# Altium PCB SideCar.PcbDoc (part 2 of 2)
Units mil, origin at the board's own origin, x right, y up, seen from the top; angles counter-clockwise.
Board outline 4800 x 2800 mil, 4 copper layers (Top Layer, GND Plane, Power Routing, Bottom Layer), stack 61.4 mil thick; 116 components, 136 nets, 590 pads, 115 vias.
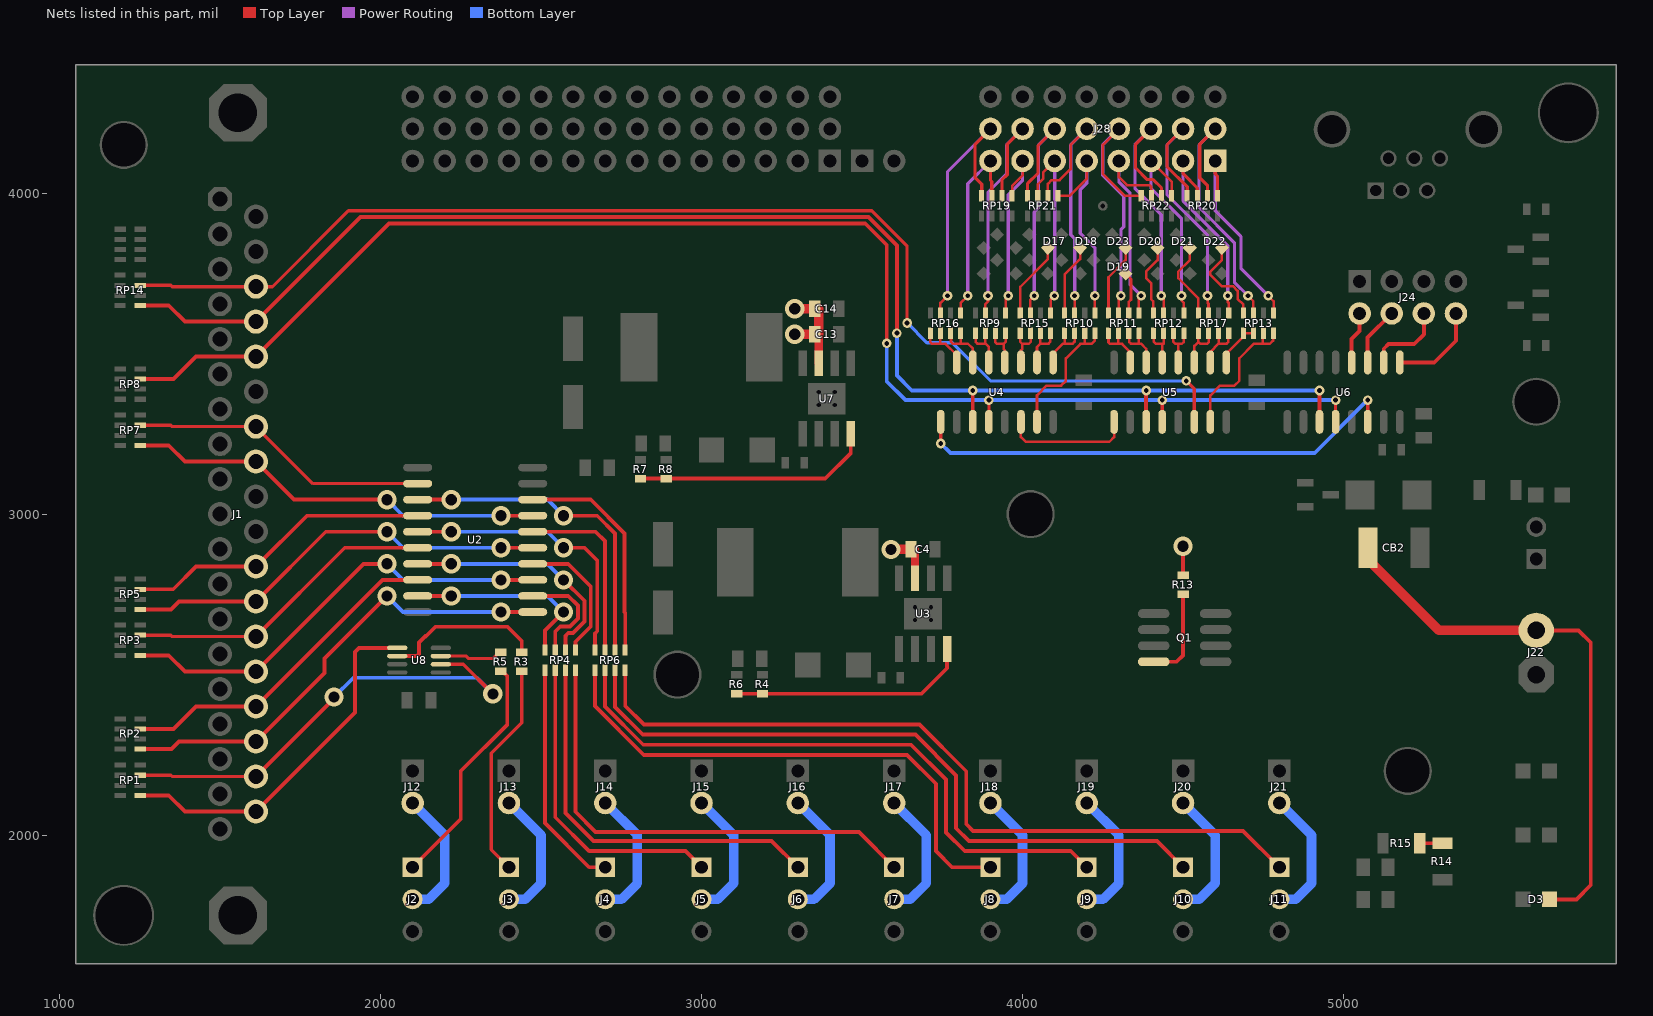
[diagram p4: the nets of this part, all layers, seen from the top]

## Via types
v1: diameter 60, hole 35, Top Layer to Bottom Layer, 60 vias
v2: diameter 30, hole 15, Top Layer to Bottom Layer, 39 vias
v3: diameter 35, hole 15, Top Layer to Bottom Layer, 10 vias
v4: diameter 40, hole 20, Top Layer to Bottom Layer, 6 vias

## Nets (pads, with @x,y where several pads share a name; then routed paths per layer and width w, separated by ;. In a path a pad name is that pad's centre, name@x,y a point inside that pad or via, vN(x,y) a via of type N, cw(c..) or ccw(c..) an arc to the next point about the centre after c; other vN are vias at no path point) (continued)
NetD17_A: D17.A RP15.7 | length 238.4
  Top Layer w8: RP15.7@3992.76,3626.5 3992.76,3707.76 4079.12,3794.12 D17.A@4079.12,3829.12
NetD18_A: D18.A RP10.7 | length 222.7
  Top Layer w8: RP10.7@4130.75,3626.5 4130.75,3745.75 4179.12,3794.12 D18.A@4179.12,3829.12
NetD19_A: D19.A RP11.3 | length 132.5
  Top Layer w8: D19.A@4320.88,3749.12 4337.76,3732.24 4337.76,3667.76 4330.75,3660.75 RP11.3@4330.75,3626.5
NetD20_A: D20.A RP12.7 | length 226.9
  Top Layer w8: RP12.7@4407.76,3626.5 4407.76,3662.24 4400.75,3669.25 4400.75,3719.25 4385,3735 4385,3755 4420.88,3790.88 D20.A@4420.88,3829.12
NetD21_A: D21.A RP17.7 | length 243.5
  Top Layer w8: D21.A@4520.88,3829.12 4520.88,3790.88 4485,3755 4485,3735 4547.76,3672.24 RP17.7@4547.76,3626.5
NetD22_A: D22.A RP13.7 | length 280.6
  Top Layer w8: D22.A@4620.88,3829.12 4620.88,3790.88 4585,3755 4585,3745 4620,3710 4655,3710 4670,3695 4670,3670 4687.76,3652.24 RP13.7@4687.76,3626.5
NetD23_A: D23.A RP11.7 | length 224.6
  Top Layer w8: RP11.7@4267.76,3626.5 4267.76,3737.76 4320.88,3790.88 D23.A@4320.88,3829.12
NetJ2_1: J2.1 R5.1 | length 731.3
  Top Layer w12: J2.1@2100,1900 2250,2050 2250,2200 2395,2345 2395,2495 R5.1@2385,2505
NetJ2_2: J2.2 J12.2 | length 412.1
  Bottom Layer w30: J2.2@2100,1800 2150,1800 2200,1850 2200,2000 J12.2@2100,2100
NetJ3_1: J3.1 R3.1 | length 672.6
  Top Layer w10: J3.1@2400,1900 2345,1955 2345,2255 2440,2350 R3.1@2440,2510.47
NetJ3_2: J3.2 J13.2 | length 412.1
  Bottom Layer w30: J3.2@2400,1800 2450,1800 2500,1850 2500,2000 J13.2@2400,2100
NetJ4_1: J4.1 RP4.1 | length 720.4
  Top Layer w12: RP4.1@2512.76,2513.5 2512.76,2037.24 2650,1900 J4.1@2700,1900
NetJ4_2: J4.2 J14.2 | length 412.1
  Bottom Layer w30: J4.2@2700,1800 2750,1800 2800,1850 2800,2000 J14.2@2700,2100
NetJ5_1: J5.1 RP4.3 | length 978
  Top Layer w12: RP4.3@2544.25,2513.5 2544.25,2055.75 2650,1950 2950,1950 J5.1@3000,1900
NetJ5_2: J5.2 J15.2 | length 412.1
  Bottom Layer w30: J5.2@3000,1800 3050,1800 3100,1850 3100,2000 J15.2@3000,2100
NetJ6_1: J6.1 RP4.5 | length 1238.9
  Top Layer w12: RP4.5@2575.75,2513.5 2575.75,2068.79 2663.05,1981.5 3218.5,1981.5 J6.1@3300,1900
NetJ6_2: J6.2 J16.2 | length 412.1
  Bottom Layer w30: J6.2@3300,1800 3350,1800 3400,1850 3400,2000 J16.2@3300,2100
NetJ7_1: J7.1 RP4.7 | length 1505.1
  Top Layer w12: RP4.7@2607.24,2513.5 2607.24,2072.76 2670,2010 3490,2010 J7.1@3600,1900
NetJ7_2: J7.2 J17.2 | length 412.1
  Bottom Layer w30: J7.2@3600,1800 3650,1800 3700,1850 3700,2000 J17.2@3600,2100
NetJ8_1: J8.1 RP6.1 | length 1674.6
  Top Layer w12: RP6.1@2667.76,2513.5 2667.76,2402.24 2820,2250 3640,2250 3730,2160 3730,1950 3780,1900 J8.1@3900,1900
NetJ8_2: J8.2 J18.2 | length 412.1
  Bottom Layer w30: J8.2@3900,1800 3950,1800 4000,1850 4000,2000 J18.2@3900,2100
NetJ9_1: J9.1 RP6.3 | length 1917.3
  Top Layer w12: RP6.3@2699.25,2513.5 2699.25,2400.75 2818.5,2281.5 3653.05,2281.5 3761.5,2173.05 3761.5,2008.5 3820,1950 4150,1950 J9.1@4200,1900
NetJ9_2: J9.2 J19.2 | length 412.1
  Bottom Layer w30: J9.2@4200,1800 4250,1800 4300,1850 4300,2000 J19.2@4200,2100
NetJ10_1: J10.1 RP6.5 | length 2186.7
  Top Layer w12: RP6.5@2730.75,2513.5 2730.75,2399.25 2817.01,2312.99 3666.09,2312.99 3792.99,2186.09 3792.99,2021.55 3833.05,1981.5 4418.5,1981.5 J10.1@4500,1900
NetJ10_2: J10.2 J20.2 | length 412.1
  Bottom Layer w30: J10.2@4500,1800 4550,1800 4600,1850 4600,2000 J20.2@4500,2100
NetJ11_1: J11.1 RP6.7 | length 2453.1
  Top Layer w12: RP6.7@2762.24,2513.5 2762.24,2402.76 2820.51,2344.49 3679.14,2344.49 3824.49,2199.14 3824.49,2034.6 3846.09,2012.99 4687.01,2012.99 J11.1@4800,1900
NetJ11_2: J11.2 J21.2 | length 412.1
  Bottom Layer w30: J11.2@4800,1800 4850,1800 4900,1850 4900,2000 J21.2@4800,2100
NetJ24_2: J24.2 U6.4 | length 162.8
  Top Layer w12: U6.4@5025,3472.52 5025,3545 5050,3570 J24.2@5050,3625
NetJ24_4: J24.4 U6.3 | length 183.5
  Top Layer w12: U6.3@5075,3472.52 5075,3550 J24.4@5150,3625
NetJ24_6: J24.6 U6.2 | length 251.1
  Top Layer w12: U6.2@5125,3472.52 5125,3515 5140,3530 5220,3530 5250,3560 J24.6@5250,3625
NetJ24_8: J24.8 U6.1 | length 288
  Top Layer w12: U6.1@5175,3472.52 5282.52,3472.52 5350,3540 J24.8@5350,3625
NetQ1_G: Q1.G R13.1 | length 289.7
  Top Layer w12: Q1.G@4408.54,2540 4480,2540 4500,2560 R13.1@4500,2750
NetR3_2: R3.2 U8.6 | length 500.7
  Top Layer w12: U8.6@2052.09,2557.8 2113.11,2557.8 2120,2564.69 2120,2600 2140,2620 ; 2140,2617.83 2171.42,2649.25 2395.75,2649.25 2440,2605 R3.2@2440,2570
NetR4_1: R4.1 R6.2 U3.4 | length 747.9
  Top Layer w12: R6.2@3110,2440.47 R4.1@3190,2440.47 3685.47,2440.47 3765,2520 U3.4@3765,2580
NetR5_2: R5.2 U8.3 | length 186.5
  Top Layer w10: U8.3@2187.91,2557.8 2267.2,2557.8 2275,2550 2350,2550 R5.2@2365,2565
NetR7_2: R7.2 R8.1 U7.4 | length 747.9
  Top Layer w12: R7.2@2810,3110.47 R8.1@2890,3110.47 3385.47,3110.47 3465,3190 U7.4@3465,3250
NetR14_1: R14.1 R15.2 | length 70.8
  Top Layer w10: R15.2@5237.09,1975 R14.1@5307.91,1975
NetRP4_2: RP4.2 U2.9 | length 631.2
  Top Layer w12: U2.9@2115.87,2745 v1(2220,2745) ; RP4.2@2512.76,2576.5 2512.76,2637.76 v1(2570,2695) v1@2580,2685
  Bottom Layer w12: v1(2220,2745) 2520,2745 v1(2570,2695)
NetRP4_4: RP4.4 U2.12 | length 338.7
  Top Layer w12: U2.12@2474.13,2745 2475,2745 2585,2745 2615,2715 2615,2675 2590,2650 2560,2650 2544.25,2634.25 RP4.4@2544.25,2576.5
NetRP4_6: RP4.6 U2.7 | length 753.6
  Top Layer w12: U2.7@2115.87,2845 v1(2220,2845) ; v1(2570,2795) 2635,2730 2635,2665 2600,2630 2585,2630 2575.75,2620.75 RP4.6@2575.75,2576.5
  Bottom Layer w12: v1(2220,2845) 2520,2845 v1(2570,2795)
NetRP4_8: RP4.8 U2.14 | length 422.3
  Top Layer w12: U2.14@2480,2845 2585,2845 2655,2775 2655,2650 2607.24,2602.24 RP4.8@2607.24,2576.5
NetRP6_2: RP6.2 U2.5 | length 877.9
  Top Layer w12: U2.5@2115.87,2945 v1(2220,2945) ; v1(2570,2895) 2635,2895 2675,2855 2675,2635 2667.76,2627.76 RP6.2@2667.76,2576.5
  Bottom Layer w12: v1(2220,2945) 2520,2945 v1(2570,2895)
NetRP6_4: RP6.4 U2.16 | length 576.5
  Top Layer w12: U2.16@2474.13,2945 2670,2945 2699.25,2915.75 RP6.4@2699.25,2576.5
NetRP6_6: RP6.6 U2.3 | length 1021.4
  Top Layer w12: U2.3@2115.87,3045 v1(2220,3045) ; v1(2570,2995) 2675,2995 2730.75,2939.25 RP6.6@2730.75,2576.5
  Bottom Layer w12: v1(2220,3045) 2520,3045 v1(2570,2995)
NetRP6_8: RP6.8 U2.18 | length 693.8
  Top Layer w12: U2.18@2474.13,3045 2655,3045 2760,2940 2760,2695 2762.24,2692.76 RP6.8@2762.24,2576.5
NetRP9_2: RP9.2 RP9.4 U4.4 | length 233.7
  Top Layer w8: RP9.4@3915.75,3563.5 RP9.4@3914.49,3563.5 ; U4.4@3945,3472.52 3945,3510 3940.75,3514.25 3940.75,3530 ; RP9.2@3947.24,3563.5 3947.24,3536.5 3940.75,3530 ; 3914.49,3536.5 RP9.4@3914.49,3563.5 ; 3914.49,3536.5 RP9.4@3914.49,3563.5 ; 3914.49,3536.5 RP9.4@3914.49,3563.5 ; 3914.49,3536.5 RP9.4@3914.49,3563.5 ; 3914.49,3536.5 3920.98,3530 3940.75,3530
NetRP9_6: RP9.6 RP9.8 U4.5 | length 242.7
  Top Layer w8: RP9.8@3852.76,3563.5 RP9.8@3854.02,3564.76 ; RP9.6@3884.25,3563.5 3884.25,3531.26 ; U4.5@3895,3472.52 3895,3520.51 3884.25,3531.26 ; 3854.02,3536.5 RP9.8@3854.02,3563.5 ; 3854.02,3536.5 RP9.8@3854.02,3563.5 ; 3854.02,3536.5 RP9.8@3854.02,3563.5 ; 3854.02,3536.5 RP9.8@3854.02,3563.5 ; 3854.02,3536.5 3859.25,3531.26 3884.25,3531.26 ; RP9.8@3854.02,3563.5 RP9.8@3854.02,3564.76 ; RP9.8@3854.02,3563.5 RP9.8@3854.02,3564.76 ; RP9.8@3854.02,3563.5 RP9.8@3854.02,3564.76 ; RP9.8@3854.02,3563.5 RP9.8@3854.02,3564.76
NetRP10_2: RP10.2 RP10.4 U4.15 | length 429.8
  Top Layer w8: U4.15@4045,3287.48 4045,3370 4075,3400 4120,3400 4135,3415 4135,3485 4180,3530 4215,3530 4225.24,3540.24 RP10.2@4225.24,3563.5 ; 4193.74,3531.26 RP10.4@4193.74,3563.5
NetRP10_6: RP10.6 RP10.8 U4.1 | length 142.8
  Top Layer w8: U4.1@4095,3500 4125,3530 4129.88,3530 ; RP10.8@4130.75,3563.5 4130.75,3530.75 4129.88,3530 ; RP10.6@4162.24,3563.5 4162.24,3537.24 4155,3530 4129.88,3530
NetRP11_2: RP11.2 RP11.4 U5.6 | length 251.5
  Top Layer w8: RP11.4@4330.75,3563.5 RP11.4@4332.01,3564.76 ; RP11.2@4362.24,3563.5 4362.24,3531.26 ; U5.6@4385,3472.52 4385,3515 4368.74,3531.26 4362.24,3531.26 ; 4332.01,3536.5 RP11.4@4332.01,3563.5 ; 4332.01,3536.5 RP11.4@4332.01,3563.5 ; 4332.01,3536.5 RP11.4@4332.01,3563.5 ; 4332.01,3536.5 RP11.4@4332.01,3563.5 ; 4332.01,3536.5 4337.24,3531.26 4362.24,3531.26 ; RP11.4@4332.01,3563.5 RP11.4@4332.01,3564.76 ; RP11.4@4332.01,3563.5 RP11.4@4332.01,3564.76 ; RP11.4@4332.01,3563.5 RP11.4@4332.01,3564.76 ; RP11.4@4332.01,3563.5 RP11.4@4332.01,3564.76
NetRP11_6: RP11.6 RP11.8 U5.7 | length 172.8
  Top Layer w8: RP11.8@4267.76,3563.5 4267.76,3535.24 4272.99,3530 4297.99,3530 ; RP11.6@4297.99,3562.24 4297.99,3530 ; U5.7@4335,3472.52 4335,3505 4310,3530 4297.99,3530
NetRP12_2: RP12.2 RP12.4 U5.4 | length 230.7
  Top Layer w8: U5.4@4485,3472.52 4485,3530 ; RP12.2@4502.24,3563.5 4502.24,3536.5 4495.75,3530 4485,3530 ; 4469.49,3536.5 RP12.4@4469.49,3563.5 ; 4469.49,3536.5 RP12.4@4469.49,3563.5 ; 4469.49,3536.5 RP12.4@4469.49,3563.5 ; 4469.49,3536.5 RP12.4@4469.49,3563.5 ; 4469.49,3536.5 4475.98,3530 4485,3530
NetRP12_6: RP12.6 RP12.8 U5.5 | length 234
  Top Layer w8: RP12.8@4407.76,3563.5 RP12.8@4409.02,3564.76 ; U5.5@4435,3472.52 4435,3527.01 ; RP12.6@4439.25,3563.5 4439.25,3531.26 4414.25,3531.26 4409.02,3536.5 ; 4409.02,3536.5 RP12.8@4409.02,3563.5 ; 4409.02,3536.5 RP12.8@4409.02,3563.5 ; 4409.02,3536.5 RP12.8@4409.02,3563.5 ; 4409.02,3536.5 RP12.8@4409.02,3563.5 ; RP12.8@4409.02,3563.5 RP12.8@4409.02,3564.76 ; RP12.8@4409.02,3563.5 RP12.8@4409.02,3564.76 ; RP12.8@4409.02,3563.5 RP12.8@4409.02,3564.76 ; RP12.8@4409.02,3563.5 RP12.8@4409.02,3564.76
NetRP13_2: RP13.2 RP13.4 U5.15 | length 579.1
  Top Layer w8: U5.15@4585,3287.48 4585,3370 4615,3400 4660,3400 4675,3415 4675,3485 4720,3530 4770,3530 4780.24,3540.24 ; 4748.74,3531.26 RP13.4@4748.74,3563.5 ; 4748.74,3531.26 RP13.4@4748.74,3563.5 ; 4748.74,3531.26 RP13.4@4748.74,3563.5 ; 4780.24,3540.24 RP13.2@4780.24,3563.5 ; 4780.24,3540.24 RP13.2@4780.24,3563.5 ; 4780.24,3540.24 RP13.2@4780.24,3563.5 ; 4780.24,3540.24 RP13.2@4780.24,3563.5
NetRP13_6: RP13.6 RP13.8 U5.1 | length 144.3
  Top Layer w8: U5.1@4635,3472.52 4635,3500 4687.76,3552.76 RP13.8@4687.76,3563.5 RP13.6@4719.25,3563.5
NetRP15_2: RP15.2 RP15.4 U4.2 | length 242.7
  Top Layer w8: U4.2@4045,3472.52 4045,3520.51 4055.75,3531.26 ; RP15.4@4055.75,3563.5 4055.75,3531.26 ; RP15.2@4087.24,3563.5 RP15.2@4085.98,3564.76 ; 4055.75,3531.26 4080.75,3531.26 4085.98,3536.5 ; 4085.98,3536.5 RP15.2@4085.98,3563.5 ; 4085.98,3536.5 RP15.2@4085.98,3563.5 ; 4085.98,3536.5 RP15.2@4085.98,3563.5 ; 4085.98,3536.5 RP15.2@4085.98,3563.5 ; RP15.2@4085.98,3563.5 RP15.2@4085.98,3564.76 ; RP15.2@4085.98,3563.5 RP15.2@4085.98,3564.76 ; RP15.2@4085.98,3563.5 RP15.2@4085.98,3564.76 ; RP15.2@4085.98,3563.5 RP15.2@4085.98,3564.76
NetRP15_6: RP15.6 RP15.8 U4.3 | length 233.7
  Top Layer w8: RP15.8@3992.76,3563.5 3992.76,3536.5 3999.25,3530 ; U4.3@3995,3472.52 3995,3510 3999.25,3514.25 3999.25,3530 ; RP15.6@4024.25,3563.5 RP15.6@4025.51,3563.5 ; 3999.25,3530 4019.02,3530 4025.51,3536.5 ; 4025.51,3536.5 RP15.6@4025.51,3563.5 ; 4025.51,3536.5 RP15.6@4025.51,3563.5 ; 4025.51,3536.5 RP15.6@4025.51,3563.5 ; 4025.51,3536.5 RP15.6@4025.51,3563.5
NetRP16_2: RP16.2 RP16.4 U4.6 | length 266.8
  Top Layer w8: RP16.4@3775.75,3563.5 RP16.4@3777.01,3564.76 ; RP16.2@3807.24,3563.5 3807.24,3531.26 ; U4.6@3845,3472.52 3845,3515.51 3829.25,3531.26 3807.24,3531.26 ; 3777.01,3536.5 RP16.4@3777.01,3563.5 ; 3777.01,3536.5 RP16.4@3777.01,3563.5 ; 3777.01,3536.5 RP16.4@3777.01,3563.5 ; 3777.01,3536.5 RP16.4@3777.01,3563.5 ; 3777.01,3536.5 3782.24,3531.26 3807.24,3531.26 ; RP16.4@3777.01,3563.5 RP16.4@3777.01,3564.76 ; RP16.4@3777.01,3563.5 RP16.4@3777.01,3564.76 ; RP16.4@3777.01,3563.5 RP16.4@3777.01,3564.76 ; RP16.4@3777.01,3563.5 RP16.4@3777.01,3564.76
NetRP16_6: RP16.6 RP16.8 U4.7 | length 181.9
  Top Layer w8: RP16.8@3712.76,3563.5 3712.76,3535.24 3717.99,3530 3742.99,3530 ; RP16.6@3742.99,3562.24 3742.99,3530 ; U4.7@3795,3472.52 3795,3495 3760,3530 3742.99,3530
NetRP17_2: RP17.2 RP17.4 U5.2 | length 248.9
  Top Layer w8: U5.2@4585,3472.52 4585,3505.51 4610.75,3531.26 ; RP17.4@4610.75,3563.5 4610.75,3531.26 ; RP17.2@4642.24,3563.5 RP17.2@4640.98,3564.76 ; 4610.75,3531.26 4635.75,3531.26 4640.98,3536.5 ; 4640.98,3536.5 RP17.2@4640.98,3563.5 ; 4640.98,3536.5 RP17.2@4640.98,3563.5 ; 4640.98,3536.5 RP17.2@4640.98,3563.5 ; 4640.98,3536.5 RP17.2@4640.98,3563.5 ; RP17.2@4640.98,3563.5 RP17.2@4640.98,3564.76 ; RP17.2@4640.98,3563.5 RP17.2@4640.98,3564.76 ; RP17.2@4640.98,3563.5 RP17.2@4640.98,3564.76 ; RP17.2@4640.98,3563.5 RP17.2@4640.98,3564.76
NetRP17_6: RP17.6 RP17.8 U5.3 | length 243.7
  Top Layer w8: U5.3@4535,3472.52 4535,3523.74 4547.76,3536.5 ; RP17.8@4547.76,3563.5 4547.76,3536.5 ; RP17.6@4579.25,3563.5 RP17.6@4580.51,3563.5 ; 4547.76,3536.5 4554.25,3530 4574.02,3530 4580.51,3536.5 ; 4580.51,3536.5 RP17.6@4580.51,3563.5 ; 4580.51,3536.5 RP17.6@4580.51,3563.5 ; 4580.51,3536.5 RP17.6@4580.51,3563.5 ; 4580.51,3536.5 RP17.6@4580.51,3563.5
NetU4_9: U4.9 U6.14 | length 1545.8
  Top Layer w10: v2(3745,3219.96) U4.9@3745,3287.48 ; U6.14@5075,3287.48 v2(5075,3355)
  Bottom Layer w12: v2(3745,3219.96) 3774.96,3190 4910,3190 v2(5075,3355)
NetU4_14: U4.14 U5.9 | length 397.4
  Top Layer w8: U4.14@3995,3287.48 3995,3240 4010,3225 4270,3225 4285,3240 U5.9@4285,3287.48
PWM1: J1.26 RP7.5 U2.2 | length 939.4
  Top Layer w10: RP7.5@1251.72,3276.77 1347.23,3276.77 1351.48,3272.52 J1.26@1612,3272.5 1789.5,3095 U2.2@2115.87,3095
PWM2: J1.27 RP7.1 U2.17 | length 1313
  Top Layer w12: RP7.1@1251.72,3213.78 1340.22,3213.78 1390.48,3163.52 J1.27@1612,3163.5 1730.5,3045 v1(2020,3045) ; v1(2375,2995) U2.17@2474.13,2995
  Bottom Layer w12: v1(2020,3045) 2070,2995 v1(2375,2995)
PWM3: J1.30 RP5.5 U2.4 | length 1922.6
  Top Layer w12: U2.4@2100,2995 1770.47,2995 ; RP5.5@1251.72,2765.98 RP5.5@1252.17,2765.98 ; RP5.5@1251.72,2765.98 RP5.5@1252.17,2765.98 ; RP5.5@1251.72,2765.98 RP5.5@1252.17,2765.98 ; RP5.5@1252.17,2765.98 1354.24,2765.98 ; RP5.5@1252.17,2765.98 1354.24,2765.98 ; RP5.5@1252.17,2765.98 1354.24,2765.98 ; RP5.5@1252.17,2765.98 1354.24,2765.98 ; 1354.24,2765.98 1424.77,2836.52 J1.30@1612,2836.5 ; J1.30@1612,2836.5 1770.47,2995 ; J1.30@1612,2836.5 1770.47,2995 ; J1.30@1612,2836.5 1770.47,2995 ; J1.30@1612,2836.5 1770.47,2995
PWM4: J1.31 RP5.1 U2.15 | length 1631.7
  Top Layer w12: v1(2020,2945) 1829.5,2945 J1.31@1612,2727.5 1372.34,2727.52 1347.81,2702.99 ; v1(2375,2895) U2.15@2474.13,2895 ; RP5.1@1251.72,2702.99 RP5.1@1252.17,2702.99 ; RP5.1@1251.72,2702.99 RP5.1@1252.17,2702.99 ; RP5.1@1251.72,2702.99 RP5.1@1252.17,2702.99 ; RP5.1@1251.72,2702.99 RP5.1@1252.17,2702.99 ; RP5.1@1252.17,2702.99 1347.81,2702.99 ; RP5.1@1252.17,2702.99 1347.81,2702.99 ; RP5.1@1252.17,2702.99 1347.81,2702.99 ; RP5.1@1252.17,2702.99 1347.81,2702.99
  Bottom Layer w12: v1(2020,2945) 2070,2895 v1(2375,2895)
PWM5: J1.32 RP3.5 U2.6 | length 980.4
  Top Layer w10: RP3.5@1251.72,2622.77 1347.23,2622.77 1351.48,2618.52 J1.32@1612,2618.5
  Top Layer w12: J1.32@1612,2618.5 1888.5,2895 U2.6@2115.87,2895
PWM6: J1.33 RP3.1 U2.13 | length 2826.2
  Top Layer w12: RP3.1@1251.72,2559.78 1340.22,2559.78 1390.48,2509.52 J1.33@1612,2509.5 ; v1(2020,2845) 1947.47,2845 ; v1(2375,2795) U2.13@2474.13,2795 ; J1.33@1612,2509.5 1947.47,2845 ; J1.33@1612,2509.5 1947.47,2845 ; J1.33@1612,2509.5 1947.47,2845 ; J1.33@1612,2509.5 1947.47,2845
  Bottom Layer w12: v1(2020,2845) 2070,2795 v1(2375,2795)
PWM7: J1.34 RP2.5 U2.8 | length 1056.4
  Top Layer w12: RP2.5@1251.72,2330.75 RP2.5@1252.17,2330.75 1355,2330.75 1424.77,2400.52 J1.34@1612,2400.5 2006.5,2795 U2.8@2115.87,2795
PWM8: J1.35 RP2.1 U2.11 | length 1467.5
  Top Layer w12: RP2.1@1251.72,2267.76 RP2.1@1252.17,2267.76 1348.58,2267.76 1372.34,2291.52 J1.35@1612,2291.5 1825,2504.5 1825,2550 v1(2020,2745) ; v1(2375,2695) U2.11@2474.13,2695
  Bottom Layer w12: v1(2020,2745) 2070,2695 v1(2375,2695)
PWM9: J1.36 RP1.5 U8.2 | length 1737.6
  Top Layer w10: J1.36@1612,2182.5 1351.48,2182.52 1347.23,2186.77 ; RP1.5@1251.72,2186.77 1347.23,2186.77 ; RP1.5@1251.72,2186.77 1347.23,2186.77 ; RP1.5@1251.72,2186.77 1347.23,2186.77 ; RP1.5@1251.72,2186.77 1347.23,2186.77
  Top Layer w12: J1.36@1612,2182.5 1855,2425.5 v1(1855,2430) ; U8.2@2187.91,2532.2 2257.8,2532.2 v1(2350,2440)
  Bottom Layer w12: v1(1855,2430) 1915,2490 2300,2490 v1(2350,2440)
PWM10: J1.37 RP1.1 U8.5 | length 1319.8
  Top Layer w12: U8.5@2052.09,2583.39 1933.39,2583.39 1920,2570 1920,2381.5 J1.37@1612,2073.5 1390.48,2073.52 1340.22,2123.78 ; RP1.1@1251.72,2123.78 1340.22,2123.78 ; RP1.1@1251.72,2123.78 1340.22,2123.78 ; RP1.1@1251.72,2123.78 1340.22,2123.78
RELAY_OUTPUT_CLK: J1.24 RP8.5 U4.12 U5.12 U6.12 | length 4913.2
  Top Layer w10: U4.12@3895,3287.48 v2(3895,3355) ; U5.12@4435,3287.48 v2(4435,3355) ; U6.12@4975,3287.48 v2(4975,3355)
  Top Layer w12: v2(3576.82,3531.82) 3576.82,3838.18 3510,3905 2026.5,3905 J1.24@1612,3490.5 1424.77,3490.52 1355.24,3420.98 ; RP8.5@1251.72,3420.98 RP8.5@1252.17,3420.98 ; RP8.5@1251.72,3420.98 RP8.5@1252.17,3420.98 ; RP8.5@1251.72,3420.98 RP8.5@1252.17,3420.98 ; RP8.5@1252.17,3420.98 1355.24,3420.98 ; RP8.5@1252.17,3420.98 1355.24,3420.98 ; RP8.5@1252.17,3420.98 1355.24,3420.98 ; RP8.5@1252.17,3420.98 1355.24,3420.98
  Bottom Layer w12: v2(3576.82,3531.82) 3576.82,3413.18 3635,3355 v2(3895,3355) v2(4435,3355) v2(4975,3355)
RELAY_SERIAL_DATA: J1.22 RP14.5 U5.14 | length 3855.7
  Top Layer w10: RP14.5@1251.5,3712.76 1347.24,3712.76 1351.5,3708.5 J1.22@1612,3708.5 1663.5,3708.5 1900,3945 3530,3945 3640.46,3834.54 v2(3640.46,3595.46) ; v2(4510,3415) 4535,3390 U5.14@4535,3287.48
  Bottom Layer w10: v2(3640.46,3595.46) 3701.92,3534 3781,3534 3900,3415 v2(4510,3415)
RELAY_SHIFT_CLK: J1.23 RP14.1 U4.11 U5.11 U6.11 | length 4582.6
  Top Layer w12: RP14.1@1251.5,3649.76 1340.24,3649.76 1390.5,3599.5 J1.23@1612,3599.5 1937.5,3925 3520,3925 3608.64,3836.36 v2(3608.64,3563.64) ; U4.11@3845,3287.48 v2(3845,3385) ; U5.11@4385,3287.48 v2(4385,3385) ; U6.11@4925,3287.48 v2(4925,3385)
  Bottom Layer w12: v2(3608.64,3563.64) 3608.64,3431.36 3655,3385 v2(3845,3385) v2(4385,3385) v2(4925,3385)
RELAYOUT_A_1: J28.1 RP13.1 RP20.1 | length 660.5
  Top Layer w8: v2(4765.24,3680) 4782.24,3662.99 RP13.1@4782.24,3626.5
  Top Layer w10: J28.1@4600,4100 4600,4060 4607.24,4052.76 RP20.1@4607.24,3991.5
  Power Routing w10: J28.1@4600,4100 4600,3945 4680,3865 4680,3765.24 v2(4765.24,3680)
RELAYOUT_A_2: J28.4 RP17.1 RP20.5 | length 659.3
  Top Layer w8: v2(4639.25,3680) 4639.25,3660.75 4642.24,3657.76 RP17.1@4642.24,3626.5
  Top Layer w10: J28.4@4500,4100 4500,4060 4544.25,4015.75 RP20.5@4544.25,3991.5
  Power Routing w10: J28.4@4500,4100 4500,3975 4639.25,3835.75 v2(4639.25,3680)
RELAYOUT_A_3: J28.7 RP12.1 RP22.1 | length 651
  Top Layer w8: J28.7@4400,4100 4464.25,4035.75 RP22.1@4464.25,3991.5 ; v2(4495.24,3680) 4495.24,3664.76 4502.24,3657.76 RP12.1@4502.24,3626.5
  Power Routing w10: J28.7@4400,4100 4400,4015 4495.24,3919.76 v2(4495.24,3680)
RELAYOUT_A_4: J28.10 RP11.1 RP22.5 | length 696.5
  Top Layer w8: J28.10@4300,4100 4300,4050 4325,4025 4395,4025 4401.26,4018.74 RP22.5@4401.26,3991.5 ; RP11.1@4362.24,3626.5 4362.24,3672.99 v2(4369.25,3680)
  Power Routing w10: J28.10@4300,4100 4300,4035 4335,4000 4335,3714.25 v2(4369.25,3680)
RELAYOUT_A_5: J28.13 RP10.1 RP21.1 | length 667.5
  Top Layer w8: RP21.1@4110.24,3991.5 4146.5,3991.5 4200,4045 J28.13@4200,4100 ; RP10.1@4225.24,3626.5 v2(4225.24,3680)
  Power Routing w10: J28.13@4200,4100 4200,4030 4180,4010 4180,3875 4225.24,3829.76 v2(4225.24,3680)
RELAYOUT_A_6: J28.16 RP15.1 RP21.5 | length 609.1
  Top Layer w8: RP21.5@4047.24,3991.5 4047.24,4027.24 4065,4045 4065,4065 J28.16@4100,4100 ; RP15.1@4087.24,3626.5 4087.24,3667.99 v2(4099.25,3680)
  Power Routing w10: v2(4099.25,3680) 4100,3680.75 J28.16@4100,4100
RELAYOUT_A_7: J28.19 RP9.1 RP19.1 | length 617.4
  Top Layer w8: RP9.1@3947.24,3626.5 3947.24,3672.01 v2(3955.24,3680) ; RP19.1@3967.24,3991.5 3967.24,4022.24 4000,4055 J28.19@4000,4100
  Power Routing w10: v2(3955.24,3680) 3955.24,3995.24 4000,4040 J28.19@4000,4100
RELAYOUT_A_8: J28.22 RP16.1 RP19.5 | length 622.2
  Top Layer w8: RP16.1@3807.24,3626.5 3807.24,3657.99 v2(3829.25,3680)
  Top Layer w10: J28.22@3900,4100 3900,4040 3904.25,4035.75 RP19.5@3904.25,3991.5
  Power Routing w10: v2(3829.25,3680) 3829.25,4029.25 J28.22@3900,4100
RELAYOUT_B_1: J28.2 RP13.5 RP20.3 | length 902.5
  Top Layer w8: v2(4702.24,3680) 4719.25,3662.99 RP13.5@4719.25,3626.5
  Top Layer w10: RP20.3@4575.75,3991.5 4575.75,4024.25 4552,4048 4552,4152 J28.2@4600,4200
  Power Routing w10: J28.2@4600,4200 4550,4150 4550,3955 4660,3845 4660,3722.24 v2(4702.24,3680)
RELAYOUT_B_2: J28.5 RP17.5 RP20.7 | length 903
  Top Layer w8: v2(4576.26,3680) 4576.26,3657.99 4579.25,3655 RP17.5@4579.25,3626.5
  Top Layer w10: J28.5@4500,4200 4450,4150 4450,4082.12 4512.76,4019.36 RP20.7@4512.76,3991.5
  Power Routing w10: J28.5@4500,4200 4450,4150 4450,3995 4576.26,3868.74 v2(4576.26,3680)
RELAYOUT_B_3: J28.8 RP12.5 RP22.3 | length 904
  Top Layer w8: v2(4432.24,3680) 4439.25,3672.99 RP12.5@4439.25,3626.5
  Top Layer w10: J28.8@4400,4200 4352,4152 4352,4078 4388,4042 4406.76,4042 4432.76,4016 RP22.3@4432.76,3991.5
  Power Routing w10: J28.8@4400,4200 4350,4150 4350,4015 4432.24,3932.76 v2(4432.24,3680)
RELAYOUT_B_4: J28.11 RP11.5 RP22.7 | length 936.5
  Top Layer w8: RP11.5@4299.25,3626.5 4299.25,3672.99 v2(4306.26,3680) ; J28.11@4300,4200 4250,4150 4250,4060 4318.5,3991.5 RP22.7@4369.76,3991.5
  Power Routing w10: J28.11@4300,4200 4250,4150 4250,4055 4315,3990 4315,3895 4306.26,3886.26 v2(4306.26,3680)
RELAYOUT_B_5: J28.14 RP10.5 RP21.3 | length 872.7
  Top Layer w8: RP21.3@4078.74,3991.5 4078.74,4028.74 4090,4040 4115,4040 4150,4075 4150,4150 J28.14@4200,4200 ; RP10.5@4162.24,3626.5 v2(4162.24,3680)
  Power Routing w10: v2(4162.24,3680) 4162.24,3857.76 4150,3870 4150,4150 J28.14@4200,4200
RELAYOUT_B_6: J28.17 RP15.5 RP21.7 | length 848.3
  Top Layer w8: RP15.5@4024.25,3626.5 4024.25,3667.99 v2(4036.26,3680)
  Top Layer w10: RP21.7@4015.75,3991.5 4015.75,4030 4048,4062.25 4048,4148 J28.17@4100,4200
  Power Routing w10: v2(4036.26,3680) 4036.26,3941.26 4050,3955 4050,4150 J28.17@4100,4200
RELAYOUT_B_7: J28.20 RP9.5 RP19.3 | length 856.6
  Top Layer w8: RP9.5@3884.25,3626.5 3884.25,3654.25 3892.24,3662.24 v2(3892.24,3680)
  Top Layer w10: RP19.3@3935.75,3991.5 3935.75,4040.75 3952,4057 3952,4152 J28.20@4000,4200
  Power Routing w10: v2(3892.24,3680) 3892.24,4002.24 3950,4060 3950,4150 J28.20@4000,4200
RELAYOUT_B_8: J28.23 RP16.5 RP19.7 | length 875
  Top Layer w8: RP16.5@3744.25,3626.5 3744.25,3657.99 v2(3766.26,3680)
  Top Layer w10: RP19.7@3872.76,3991.5 3872.76,4027.24 3852,4048 3852,4152 J28.23@3900,4200
  Power Routing w10: v2(3766.26,3680) 3766.26,4066.26 J28.23@3900,4200
VBATT: C4.2 C13.2 C14.2 CB2.2 D3.A J22.2 R13.2 U3.7 U7.7 | length 3023.7
  Top Layer w12: R13.2@4500,2809.06 v1(4500,2900) ; J22.2@5600,2637.8 5732.2,2637.8 5770,2600 5770,1845 5725,1800 D3.A@5641.34,1800
  Top Layer w26: U7.7@3365,3470 C13.2@3365,3560 ; U7.7@3365,3470 C13.2@3365,3560 ; U7.7@3365,3470 C13.2@3365,3560 ; U7.7@3365,3470 C13.2@3365,3560 ; U3.7@3665,2800 C4.2@3665,2890 ; U3.7@3665,2800 C4.2@3665,2890 ; U3.7@3665,2800 C4.2@3665,2890 ; U3.7@3665,2800 C4.2@3665,2890
  Top Layer w30: v1(3290,3560) C13.2@3352.6,3560 ; v1(3290,3640) C14.2@3352.6,3640 ; v1(3590,2890) C4.2@3652.6,2890 ; CB2.2@5075,2860 5297.2,2637.8 J22.2@5600,2637.8 ; C13.2@3365,3560 C14.2@3365,3640 ; C13.2@3365,3560 C14.2@3365,3640 ; C13.2@3365,3560 C14.2@3365,3640 ; C13.2@3365,3560 C14.2@3365,3640
pads on no net: J1. J1.19 J25.1 J25.MH RP18.6 RP18.8 U3.2 U3.3 U3.5 U6.5 U6.6 U6.7 U6.9 U7.2 U7.3 U7.5

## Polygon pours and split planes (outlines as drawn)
GND on Top Layer "Top Layer-No Net" (solid, remove dead copper, pour order 1000): 4520,2260 3800,2260 3800,2900 4520,2900
GND on Top Layer "6V Heat Sink" (solid, remove dead copper, pour order 1001): 3590,2630 3800,2630 3800,2400 4040,2400 4040,2900 3800,2900 3800,2750 3590,2750
GND on Top Layer "5V Heat Sink" (solid, remove dead copper, pour order 1003): 3290,3300 3500,3300 3500,3020 3700,3020 3700,3470 3500,3470 3500,3420 3290,3420
GND on Top Layer "6V cap GND Pour" (solid, remove dead copper, pour order 1005): 2790,2585 3220,2585 3220,2900 2790,2900
BATT_GND on Top Layer "Top Layer-BATT_GND" (solid, remove dead copper, pour order 1007): 5780,2640 5780,2260 4535,2260 4535,2860 5075,2860 5297.2,2637.8
GND on Top Layer "6V cap GND Pour" (solid, remove dead copper, pour order 1006): 2400,3255 2920,3255 2920,3615 2400,3615
6V on Power Routing "6V feed pour" (solid, remove dead copper, pour order 1004): 2700,2400 2700,3000 3300,3000 3300,2400
5V on Power Routing "5v main pour" (solid, remove dead copper, pour order 1010): 1070,1620 5830,1620 5830,4380 1070,4380 1070,1620
VBATT on Power Routing "VBATT Pour" (solid, remove dead copper, pour order 1009): 2900,2950 2900,3750 3550,3750 3550,3275 3725,3100 5675,3100 5675,2400 3200,2400 3200,2950
GND on Bottom Layer "GND bottom pour" (solid, remove dead copper, pour order 1000): 1070,1620 1070,4380 5830,4380 5830,1620 1070,1620
6V on Bottom Layer "6V bottom pour" (solid, remove dead copper, pour order 1002): 1900,2400 1900,2150 5000,2150 5000,2400
GND on GND Plane (split plane): 5829.9,1620.1 1070.1,1620.1 1070.1,4379.9 5829.9,4379.9

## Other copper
Top Layer:
  rectangle net GND: 2935,3135 3130,3350
  rectangle net GND: 3235,2465 3430,2680
  region net NetC1_2: 3635,2845 3490,2845 3490,2750 3635,2750
  region net NetC8_2: 3335,3515 3190,3515 3190,3420 3335,3420
  region net 6V: 3049,2956 2911,2975 2911,2838 3049,2744
  region net 5V: 2610,3615 2750,3625 2750,3415 2610,3480
Power Routing:
  rectangle net 6V: 2000,2150 4900,2400
  pour cut-out: 3900,4245.39 4600,4245.39 4600,4154.61 3900,4154.61
  pour cut-out: 3766.26,3700 4765,3700 4765.24,3654.51 3766.26,3654.51

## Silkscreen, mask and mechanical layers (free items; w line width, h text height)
Top Overlay:
  lines w10: 3976.61,2738.89 cw(c3976.61,2654.39) 4036.36,2714.14 ; 3985.25,2640.25 cw(c4045,2580.5) 4045,2665 ; 4040.25,2814.75 cw(c3980.5,2755) 4065,2755 ; 4060,2680 ccw(c4100,2720) 4140,2680 ; 4061.11,2576.61 cw(c4145.61,2576.61) 4085.86,2636.36 ; 4080,2720 4080,2740 ; 4114.14,2763.64 ccw(c4054.39,2823.39) 4138.89,2823.39 ; 4120,2720 4120,2740 ; 4135,2645 ccw(c4219.5,2645) 4159.75,2585.25 ; 4155,2735 ccw(c4155,2819.5) 4214.75,2759.75 ; 4163.64,2685.86 ccw(c4223.39,2745.61) 4223.39,2661.11
  text "I2C" at 4860,4160 h60 r90
  text "GPIO" at 2010,4100 h60 r90
  text "RELAY" at 3810,4060 h60 r90
  text "RP19-22" at 4640,3960 h50 r315
  text "D15-22" at 3490,3820 h50
  text "D8-14" at 3490,3750 h50
  text "Digital Side Car" at 1830,3710 h60
  text "RP9-17" at 3490,3680 h50
  text "Rev 8" at 1830,3600 h60
  text "EJVW" at 1830,3500 h60
  text ".print_Date" at 1840,3400 h60
  text "PWM" at 1890,1890 h60 r270
Mechanical 1:
  region: 6106.66,3401.75 9992.83,3401.75 9992.83,3388.42 6106.66,3388.42
  region: 7741.72,3388.42 7755.04,3388.42 7755.04,1312.91 7741.72,1312.91
  region: 6126.64,3702.71 8657.48,3702.71 8657.48,3689.38 6126.64,3689.38
  region: 6126.64,3729.39 8657.48,3729.39 8657.48,3716.05 6126.64,3716.05
  region: 8657.48,3729.39 8670.8,3729.39 8670.8,3716.05 8657.48,3716.05
  region: 8657.48,3702.71 8697.44,3702.71 8697.44,3689.38 8657.48,3689.38
  region: 6126.64,4237.84 8657.48,4237.84 8657.48,4224.51 6126.64,4224.51
  region: 6126.64,4264.52 8657.48,4264.52 8657.48,4251.18 6126.64,4251.18
  region: 8657.48,4264.52 8697.44,4264.52 8697.44,4251.18 8657.48,4251.18
  region: 8657.48,4237.84 8670.8,4237.84 8670.8,4224.51 8657.48,4224.51
  region: 8684.12,4224.51 8697.44,4224.51 8697.44,3729.39 8684.12,3729.39
  region: 8657.48,4224.51 8670.8,4224.51 8670.8,3729.39 8657.48,3729.39
  region: 6113.32,4224.51 6126.64,4224.51 6126.64,3729.39 6113.32,3729.39
  region: 6086.68,4224.51 6100,4224.51 6100,3729.39 6086.68,3729.39
  region: 8657.48,3729.39 8670.8,3729.39 8670.8,3716.05 8657.48,3716.05
  region: 8684.12,3729.39 8697.44,3729.39 8697.44,3689.38 8684.12,3689.38
  region: 6086.68,3729.39 6100,3729.39 6100,3689.38 6086.68,3689.38
  region: 6113.32,3729.39 6126.64,3729.39 6126.64,3716.05 6113.32,3716.05
  region: 8684.12,4264.52 8697.44,4264.52 8697.44,4224.51 8684.12,4224.51
  region: 8657.48,4237.84 8670.8,4237.84 8670.8,4224.51 8657.48,4224.51
  region: 6086.68,3702.71 6126.64,3702.71 6126.64,3689.38 6086.68,3689.38
  region: 6113.32,3729.39 6126.64,3729.39 6126.64,3716.05 6113.32,3716.05
  region: 6113.32,4237.84 6126.64,4237.84 6126.64,4224.51 6113.32,4224.51
  region: 6086.68,4264.52 6100,4264.52 6100,4224.51 6086.68,4224.51
  region: 6113.32,4237.84 6126.64,4237.84 6126.64,4224.51 6113.32,4224.51
  region: 6086.68,4264.52 6126.64,4264.52 6126.64,4251.18 6086.68,4251.18
  lines w1.67: 6106.66,3401.75 9992.83,3401.75 ; 7741.72,1312.91 7741.72,3388.42
  lines w22: 1050,1600 1050,4400 5850,4400 5850,1600 1050,1600
  text "P" at 6133.3,4100.95 h148.77
  text "r" at 6224.99,4100.95 h148.77
  text "o" at 6271.67,4100.95 h148.77
  text "j" at 6348.35,4100.95 h148.77
  text "e" at 6380.03,4100.95 h148.77
  text "c" at 6456.71,4100.95 h148.77
  text "t" at 6526.73,4100.95 h148.77
  text "P" at 7325.46,4100.95 h148.77
  text "h" at 7417.15,4100.95 h148.77
  text "o" at 7493.83,4100.95 h148.77
  text "e" at 7570.52,4100.95 h148.77
  text "n" at 7647.21,4100.95 h148.77
  text "i" at 7723.89,4100.95 h148.77
  text "x" at 7753.9,4100.95 h148.77
  text "B" at 6133.3,3929.24 h148.77
  text "o" at 6224.99,3929.24 h148.77
  text "a" at 6301.68,3929.24 h148.77
  text "r" at 6378.36,3929.24 h148.77
  text "d" at 6425.04,3929.24 h148.77
  text "D" at 7325.46,3929.24 h148.77
  text "i" at 7425.48,3929.24 h148.77
  text "g" at 7455.49,3929.24 h148.77
  text "i" at 7532.18,3929.24 h148.77
  text "t" at 7562.18,3929.24 h148.77
  text "a" at 7600.53,3929.24 h148.77
  text "l" at 7677.21,3929.24 h148.77
  text "S" at 7745.56,3929.24 h148.77
  text "i" at 7837.25,3929.24 h148.77
  text "d" at 7867.26,3929.24 h148.77
  text "e" at 7943.94,3929.24 h148.77
  text "C" at 8058.97,3929.24 h148.77
  text "a" at 8159,3929.24 h148.77
  text "r" at 8235.68,3929.24 h148.77
  text "R" at 6133.3,3760.87 h148.77
  text "e" at 6233.33,3760.87 h148.77
  text "v" at 6310.01,3760.87 h148.77
  text "8" at 7325.46,3760.87 h148.77
  text "C" at 6133.3,3433.24 h148.77
  text "o" at 6233.33,3433.24 h148.77
  text "n" at 6310.01,3433.24 h148.77
  text "s" at 6386.7,3433.24 h148.77
  text "t" at 6456.71,3433.24 h148.77
  text "r" at 6495.06,3433.24 h148.77
  text "u" at 6541.73,3433.24 h148.77
  text "c" at 6618.42,3433.24 h148.77
  text "t" at 6688.44,3433.24 h148.77
  text "i" at 6726.78,3433.24 h148.77
  text "o" at 6756.79,3433.24 h148.77
  text "n" at 6833.47,3433.24 h148.77
  text "L" at 6133.3,3261.53 h148.77
  text "a" at 6209.99,3261.53 h148.77
  text "y" at 6286.67,3261.53 h148.77
  text "e" at 6351.69,3261.53 h148.77
  text "r" at 6428.37,3261.53 h148.77
  text "s" at 6475.05,3261.53 h148.77
  text "4" at 7775.02,3261.53 h148.77
  text "F" at 6133.3,3093.15 h148.77
  text "i" at 6218.32,3093.15 h148.77
  text "n" at 6248.33,3093.15 h148.77
  text "i" at 6325.01,3093.15 h148.77
  text "s" at 6355.02,3093.15 h148.77
  text "h" at 6425.04,3093.15 h148.77
  text "e" at 6501.72,3093.15 h148.77
  text "d" at 6578.41,3093.15 h148.77
  text "T" at 6693.44,3093.15 h148.77
  text "h" at 6780.13,3093.15 h148.77
  text "i" at 6856.81,3093.15 h148.77
  text "c" at 6886.82,3093.15 h148.77
  text "k" at 6956.84,3093.15 h148.77
  text "n" at 7028.52,3093.15 h148.77
  text "e" at 7105.21,3093.15 h148.77
  text "s" at 7181.89,3093.15 h148.77
  text "s" at 7251.91,3093.15 h148.77
  text "0" at 7775.02,3093.15 h148.77
  text "6" at 7851.7,3093.15 h148.77
  text "2" at 7928.39,3093.15 h148.77
  text "+" at 8043.42,3093.15 h148.77
  text "/" at 8123.44,3093.15 h148.77
  text "-" at 8161.78,3093.15 h148.77
  text "3" at 8246.8,3093.15 h148.77
  text "0" at 8323.48,3093.15 h148.77
  text "%" at 8400.17,3093.15 h148.77
  text "S" at 6133.3,2898.1 h148.77
  text "o" at 6224.99,2898.1 h148.77
  text "l" at 6301.68,2898.1 h148.77
  text "d" at 6331.68,2898.1 h148.77
  text "e" at 6408.37,2898.1 h148.77
  text "r" at 6485.05,2898.1 h148.77
  text "M" at 6570.07,2898.1 h148.77
  text "a" at 6685.1,2898.1 h148.77
  text "s" at 6761.79,2898.1 h148.77
  text "k" at 6831.81,2898.1 h148.77
  text "U" at 7775.02,2898.1 h148.77
  text "n" at 7875.04,2898.1 h148.77
  text "s" at 7951.73,2898.1 h148.77
  text "p" at 8021.74,2898.1 h148.77
  text "e" at 8098.43,2898.1 h148.77
  text "c" at 8175.11,2898.1 h148.77
  text "i" at 8245.13,2898.1 h148.77
  text "f" at 8275.14,2898.1 h148.77
  text "i" at 8315.15,2898.1 h148.77
  text "e" at 8345.16,2898.1 h148.77
  text "d" at 8421.84,2898.1 h148.77
  text "C" at 8536.87,2898.1 h148.77
  text "o" at 8636.9,2898.1 h148.77
  text "l" at 8713.58,2898.1 h148.77
  text "o" at 8743.59,2898.1 h148.77
  text "r" at 8820.27,2898.1 h148.77
  text "T" at 7775.02,2726.4 h148.77
  text "o" at 7861.7,2726.4 h148.77
  text "p" at 7938.39,2726.4 h148.77
  text "&" at 8053.42,2726.4 h148.77
  text "B" at 8183.45,2726.4 h148.77
  text "o" at 8275.14,2726.4 h148.77
  text "t" at 8351.83,2726.4 h148.77
  text "t" at 8390.17,2726.4 h148.77
  text "o" at 8428.51,2726.4 h148.77
  text "m" at 8505.2,2726.4 h148.77
  text "S" at 6133.3,2554.69 h148.77
  text "i" at 6224.99,2554.69 h148.77
  text "l" at 6255,2554.69 h148.77
  text "k" at 6285,2554.69 h148.77
  text "S" at 6395.03,2554.69 h148.77
  text "c" at 6486.72,2554.69 h148.77
  text "r" at 6556.74,2554.69 h148.77
  text "e" at 6603.42,2554.69 h148.77
  text "e" at 6680.1,2554.69 h148.77
  text "n" at 6756.79,2554.69 h148.77
  text "U" at 7775.02,2554.69 h148.77
  text "n" at 7875.04,2554.69 h148.77
  text "s" at 7951.73,2554.69 h148.77
  text "p" at 8021.74,2554.69 h148.77
  text "e" at 8098.43,2554.69 h148.77
  text "c" at 8175.11,2554.69 h148.77
  text "i" at 8245.13,2554.69 h148.77
  text "f" at 8275.14,2554.69 h148.77
  text "i" at 8315.15,2554.69 h148.77
  text "e" at 8345.16,2554.69 h148.77
  text "d" at 8421.84,2554.69 h148.77
  text "C" at 8536.87,2554.69 h148.77
  text "o" at 8636.9,2554.69 h148.77
  text "l" at 8713.58,2554.69 h148.77
  text "o" at 8743.59,2554.69 h148.77
  text "r" at 8820.27,2554.69 h148.77
  text "T" at 7775.02,2382.98 h148.77
  text "o" at 7861.7,2382.98 h148.77
  text "p" at 7938.39,2382.98 h148.77
  text "O" at 8053.42,2382.98 h148.77
  text "n" at 8161.78,2382.98 h148.77
  text "l" at 8238.46,2382.98 h148.77
  text "y" at 8268.47,2382.98 h148.77
  text "-" at 8371.83,2382.98 h148.77
  text "I" at 8456.85,2382.98 h148.77
  text "g" at 8495.19,2382.98 h148.77
  text "n" at 8571.88,2382.98 h148.77
  text "o" at 8648.56,2382.98 h148.77
  text "r" at 8725.25,2382.98 h148.77
  text "e" at 8771.93,2382.98 h148.77
  text "B" at 8886.96,2382.98 h148.77
  text "o" at 8978.65,2382.98 h148.77
  text "t" at 9055.33,2382.98 h148.77
  text "t" at 9093.67,2382.98 h148.77
  text "o" at 9132.02,2382.98 h148.77
  text "m" at 9208.7,2382.98 h148.77
  text "S" at 9365.41,2382.98 h148.77
  text "i" at 9457.1,2382.98 h148.77
  text "l" at 9487.1,2382.98 h148.77
  text "k" at 9517.11,2382.98 h148.77
  text "C" at 6133.3,2211.27 h148.77
  text "o" at 6233.33,2211.27 h148.77
  text "p" at 6310.01,2211.27 h148.77
  text "p" at 6386.7,2211.27 h148.77
  text "e" at 6463.38,2211.27 h148.77
  text "r" at 6540.07,2211.27 h148.77
  text "W" at 6625.09,2211.27 h148.77
  text "e" at 6763.46,2211.27 h148.77
  text "i" at 6840.14,2211.27 h148.77
  text "g" at 6870.15,2211.27 h148.77
  text "h" at 6946.83,2211.27 h148.77
  text "t" at 7023.52,2211.27 h148.77
  text "1" at 7775.02,2211.27 h148.77
  text "/" at 7851.7,2211.27 h148.77
  text "2" at 7890.04,2211.27 h148.77
  text "o" at 8005.07,2211.27 h148.77
  text "z" at 8081.76,2211.27 h148.77
  text "o" at 8186.78,2211.27 h148.77
  text "r" at 8263.47,2211.27 h148.77
  text "t" at 8348.49,2211.27 h148.77
  text "h" at 8386.83,2211.27 h148.77
  text "i" at 8463.52,2211.27 h148.77
  text "c" at 8493.53,2211.27 h148.77
  text "k" at 8563.54,2211.27 h148.77
  text "e" at 8635.23,2211.27 h148.77
  text "r" at 8711.91,2211.27 h148.77
  text "T" at 6133.3,1867.85 h148.77
  text "o" at 6219.99,1867.85 h148.77
  text "p" at 6296.67,1867.85 h148.77
  text "L" at 6411.7,1867.85 h148.77
  text "a" at 6488.39,1867.85 h148.77
  text "y" at 6565.07,1867.85 h148.77
  text "e" at 6630.09,1867.85 h148.77
  text "r" at 6706.77,1867.85 h148.77
  text "." at 7775.02,1867.85 h148.77
  text "g" at 7813.36,1867.85 h148.77
  text "t" at 7890.04,1867.85 h148.77
  text "l" at 7928.39,1867.85 h148.77
  text "G" at 6133.3,1696.14 h148.77
  text "N" at 6241.66,1696.14 h148.77
  text "D" at 6341.69,1696.14 h148.77
  text "P" at 6480.05,1696.14 h148.77
  text "l" at 6571.74,1696.14 h148.77
  text "a" at 6601.75,1696.14 h148.77
  text "n" at 6678.43,1696.14 h148.77
  text "e" at 6755.12,1696.14 h148.77
  text "." at 7775.02,1696.14 h148.77
  text "g" at 7813.36,1696.14 h148.77
  text "p" at 7890.04,1696.14 h148.77
  text "1" at 7966.73,1696.14 h148.77
  text "P" at 6133.3,1524.43 h148.77
  text "o" at 6224.99,1524.43 h148.77
  text "w" at 6301.68,1524.43 h148.77
  text "e" at 6400.03,1524.43 h148.77
  text "r" at 6476.72,1524.43 h148.77
  text "R" at 6561.74,1524.43 h148.77
  text "o" at 6661.76,1524.43 h148.77
  text "u" at 6738.45,1524.43 h148.77
  text "t" at 6815.13,1524.43 h148.77
  text "i" at 6853.48,1524.43 h148.77
  text "n" at 6883.49,1524.43 h148.77
  text "g" at 6960.17,1524.43 h148.77
  text "." at 7775.02,1524.43 h148.77
  text "g" at 7813.36,1524.43 h148.77
  text "1" at 7890.04,1524.43 h148.77
  text "B" at 6133.3,1352.72 h148.77
  text "o" at 6224.99,1352.72 h148.77
  text "t" at 6301.68,1352.72 h148.77
  text "t" at 6340.02,1352.72 h148.77
  text "o" at 6378.36,1352.72 h148.77
  text "m" at 6455.05,1352.72 h148.77
  text "L" at 6611.75,1352.72 h148.77
  text "a" at 6688.44,1352.72 h148.77
  text "y" at 6765.12,1352.72 h148.77
  text "e" at 6830.14,1352.72 h148.77
  text "r" at 6906.82,1352.72 h148.77
  text "." at 7775.02,1352.72 h148.77
  text "g" at 7813.36,1352.72 h148.77
  text "b" at 7890.04,1352.72 h148.77
  text "l" at 7966.73,1352.72 h148.77
Drill Drawing:
  text ".legend" at 6100,4400 h20

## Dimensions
1050,1600 to 1050,4400 on Mechanical 1
5850,1600 to 1050,1600 on Mechanical 1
